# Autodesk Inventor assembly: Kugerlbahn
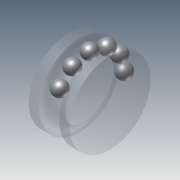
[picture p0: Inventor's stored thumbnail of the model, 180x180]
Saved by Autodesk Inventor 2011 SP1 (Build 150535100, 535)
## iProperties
Created: 2011-01
Part Number: Kugerlbahn
Document SubType Name: Assembly
Designer: Administrator
Author: Administrator
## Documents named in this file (3)
- C:\Dokumente und Einstellungen\Administrator\Desktop\Kugerlbahn.iam
- C:\Dokumente und Einstellungen\Administrator\Desktop\Rolle.ipt
- C:\Dokumente und Einstellungen\Administrator\Desktop\Kugel.ipt
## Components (7 placed, 2 different names)
1. Rolle:1 — Tangential:1, Tangential:2, Winkel:1, Passend:1
2. Kugel:1 — Tangential:1, Tangential:2, Winkel:1, Passend:1
3. Kugel:2
4. Kugel:3
5. Kugel:4
6. Kugel:5
7. Kugel:6
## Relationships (4: Tangent 2, Angle 1, Mate 1)
- Tangential:1: Rolle:1 ↔ Kugel:1
- Tangential:2: Rolle:1 ↔ Kugel:1
- Winkel:1 [Angle]: Rolle:1 ↔ Kugel:1
- Passend:1 [Mate]: Rolle:1 ↔ Kugel:1
